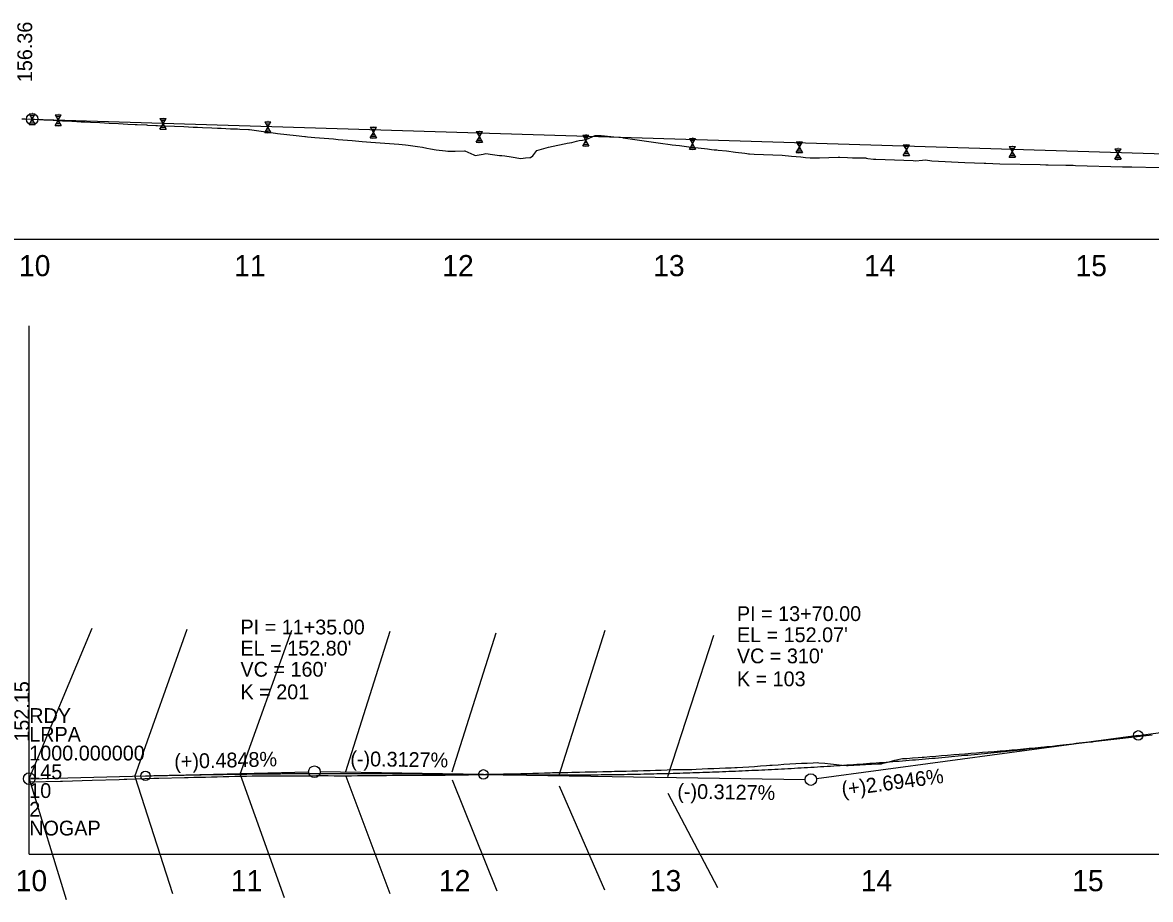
# Model space of a CAD drawing. Extents: x 573468 to 580768, y -57414 to -51768.
# Drawn here: x 573765 to 574299, y -54004 to -53589 of the extents above; entities that cross this region are included whole.
import ezdxf

# ---------------------------------------------------------------- set-up
doc = ezdxf.new("R2010")
doc.units = 0
for name, color, linetype in [('Exist Profile Cell', 7, 'Continuous'), ('Exist Vertical Profile Ground Line', 7, 'Continuous'), ('Exist Vertical Profile Horizontal Axis Label Major', 7, 'Continuous'), ('Pattern 2', 7, 'Continuous'), ('Prop Vertical Profile Curve Label', 7, 'Continuous'), ('Prop Vertical Profile Grade', 7, 'Continuous'), ('Prop Vertical Profile Grade Label', 7, 'Continuous'), ('Prop VPI Label', 7, 'Continuous'), ('Scratch_Level_2', 7, 'Continuous')]:
    doc.layers.add(name, color=color, linetype=linetype)

msp = doc.modelspace()

# ---------------------------------------------------------------- linework, layer by layer
at = {"layer": 'Exist Profile Cell'}
for p, q in [((573531.99, -53691.24), (576075.95, -53691.24)), ((573768.56, -53982.27), (573768.56, -53732.27)), ((573768.56, -53982.27), (574901.26, -53982.27)), ((573768.56, -53982.27), (573768.56, -53982.27))]:
    msp.add_line(p, q, dxfattribs=at)
at = {"layer": 'Exist Vertical Profile Ground Line'}
for points in [[(573765.07, -53634.27), (573766.54, -53634.33), (573770.15, -53634.46), (573770.97, -53634.51), (573775.39, -53634.73), (573779.82, -53634.95), (573784.24, -53635.17), (573788.67, -53635.4), (573789.01, -53635.41), (573793.1, -53635.63), (573793.67, -53635.66), (573794.01, -53635.68), (573794.97, -53635.73), (573797.52, -53635.86), (573801.95, -53636.08), (573806.37, -53636.3), (573810.8, -53636.52), (573815.22, -53636.75), (573818.64, -53636.93), (573819.65, -53636.97), (573824.07, -53637.19), (573824.55, -53637.21), (573828.5, -53637.41), (573829.22, -53637.45), (573832.92, -53637.6), (573837.35, -53637.78)], [(573837.35, -53637.78), (573841.77, -53637.96), (573846.2, -53638.15), (573848.2, -53638.23), (573850.63, -53638.35), (573855.05, -53638.56), (573857.64, -53638.69), (573859.48, -53638.76), (573863.9, -53638.94), (573867.13, -53639.07), (573868.33, -53639.13), (573872.39, -53639.34), (573872.75, -53639.39), (573877.18, -53640), (573881.6, -53640.6), (573885.06, -53641.07), (573886.03, -53641.18), (573890.45, -53641.66), (573894.88, -53642.14), (573898.98, -53642.58), (573899.31, -53642.62), (573900.28, -53642.74), (573903.73, -53643.04), (573908.16, -53643.43), (573912.58, -53643.82), (573914.76, -53644), (573917.01, -53644.2), (573921.43, -53644.57), (573923.07, -53644.7), (573926.15, -53644.93), (573930.28, -53645.26), (573934.71, -53645.61), (573939.13, -53645.95), (573943.56, -53646.28), (573946.67, -53646.52), (573947.98, -53646.71), (573952.41, -53647.33), (573954.69, -53647.65), (573956.84, -53648.13), (573958.5, -53648.51), (573961.26, -53648.87), (573965.69, -53649.44), (573966.66, -53649.56), (573970.11, -53649.5), (573974.54, -53649.41), (573974.84, -53649.41), (573978.96, -53651.33), (573979.62, -53651.63), (573983.39, -53650.96), (573984.76, -53650.71), (573987.81, -53651.14), (573991.13, -53651.61), (573992.24, -53651.7), (573993.65, -53651.84), (573996.66, -53652.3), (574001.22, -53653.08), (574003.48, -53652.77), (574005.52, -53652.54), (574005.86, -53652.5), (574007.02, -53651.82), (574008.78, -53649.28), (574009.94, -53648.95), (574014.37, -53647.67), (574018.79, -53646.73), (574022.51, -53645.95), (574023.22, -53645.84), (574025.37, -53645.5), (574027.64, -53644.91), (574028.85, -53644.6), (574030.44, -53644.31), (574032.07, -53644.03), (574032.5, -53643.96), (574036.49, -53642.14), (574039.32, -53642.24), (574040.92, -53642.39), (574045.34, -53642.8), (574047.73, -53643.02), (574049.33, -53643.17), (574049.77, -53643.23), (574054.19, -53643.87), (574058.62, -53644.5), (574063.05, -53645.13), (574067.47, -53645.76), (574071.9, -53646.39), (574072.99, -53646.54), (574076.32, -53646.96), (574080.75, -53647.51), (574082.04, -53647.67), (574085.17, -53648.03), (574089.6, -53648.54), (574091.47, -53648.76), (574092.73, -53648.9), (574094.02, -53649.02), (574094.7, -53649.09), (574098.62, -53649.4), (574102.87, -53649.99), (574107.3, -53650.59), (574108.2, -53650.71), (574109.08, -53650.82), (574109.45, -53650.85), (574111.72, -53650.93)], [(574111.72, -53650.93), (574116.15, -53651.1), (574120.58, -53651.26), (574125, -53651.43), (574129.43, -53651.88), (574133.85, -53652.33), (574135.97, -53652.54), (574138.28, -53652.7), (574139.65, -53652.79), (574142.7, -53652.71), (574147.13, -53652.6), (574151.55, -53652.49), (574152.35, -53652.47), (574155.98, -53652.61), (574158.31, -53652.7), (574160.4, -53652.71), (574164.52, -53652.74), (574164.83, -53652.83), (574165.49, -53653.03), (574168.24, -53653.38), (574169.26, -53653.41), (574173.68, -53653.58), (574178.11, -53653.74), (574182.53, -53653.9), (574186.96, -53654.06), (574188.17, -53654.1), (574191.38, -53653.84), (574192.77, -53653.73), (574195.81, -53654.09), (574211.43, -53654.92), (574220.55, -53655.18), (574221.36, -53655.21), (574227.98, -53655.52), (574247.06, -53655.81), (574249.75, -53655.98), (574250.98, -53656.06), (574259.21, -53656.25), (574262.76, -53656.27), (574263.91, -53656.38), (574286.08, -53656.96), (574290.51, -53656.97), (574303.67, -53657.3)], [(574264.06, -53929.85), (574266.83, -53929.55), (574269.59, -53929.25), (574271.85, -53929.01), (574272.36, -53928.95), (574275.12, -53928.62), (574277.52, -53928.33), (574277.89, -53928.29), (574280.65, -53927.97), (574283.42, -53927.66), (574286.18, -53927.34), (574288.95, -53927.03), (574291.72, -53926.73), (574294.48, -53926.42), (574297.25, -53926.12), (574300.16, -53925.8)], [(574040.14, -53943.16), (574042.83, -53943.1), (574044.25, -53943.07), (574045.6, -53943.04), (574048.36, -53942.99), (574051.13, -53942.93), (574053.89, -53942.88), (574056.66, -53942.82), (574059.42, -53942.72), (574062.19, -53942.61), (574062.54, -53942.6), (574064.95, -53942.51), (574067.72, -53942.42), (574070.48, -53942.33), (574073.25, -53942.24), (574076.02, -53942.15), (574076.65, -53942.13), (574078.78, -53942.12), (574081.55, -53942.1), (574082.22, -53942.1), (574084.31, -53942.01), (574087.08, -53941.89), (574089.84, -53941.78), (574092.61, -53941.67), (574095.37, -53941.56), (574098.14, -53941.46), (574098.88, -53941.43), (574100.9, -53941.33), (574102.61, -53941.26), (574103.67, -53941.19), (574106.43, -53941.02), (574109.2, -53940.85), (574111.97, -53940.68), (574114.81, -53940.51), (574117.5, -53940.31), (574119.11, -53940.18), (574120.26, -53940.1), (574123.03, -53939.92), (574125.79, -53939.73), (574128.56, -53939.55), (574131.47, -53939.36), (574134.09, -53939.19), (574134.51, -53939.17), (574136.52, -53939.19), (574136.85, -53939.17), (574139.62, -53939.01), (574141.6, -53938.9), (574142.38, -53938.97), (574145.15, -53939.24), (574147.92, -53939.51), (574150.68, -53939.78), (574153.45, -53940.05), (574155.43, -53940.25), (574156.21, -53940.21), (574158.98, -53940.07), (574161.74, -53939.93), (574164.51, -53939.79), (574167.27, -53939.66), (574170.04, -53939.52), (574171.97, -53939.42), (574172.8, -53939.21), (574175.57, -53938.49), (574178.33, -53937.78), (574181.13, -53937.06), (574182, -53937.03), (574183.99, -53936.93), (574186.63, -53936.73), (574189.4, -53936.51), (574191.29, -53936.37), (574192.16, -53936.29), (574194.93, -53936.05), (574197.69, -53935.81), (574200.46, -53935.57), (574203.22, -53935.33), (574206.28, -53935.07), (574208.75, -53934.89), (574211.52, -53934.7), (574213.03, -53934.59), (574214.28, -53934.49), (574217.05, -53934.26), (574219.82, -53934.04), (574222.58, -53933.82), (574225.35, -53933.6), (574228.11, -53933.38), (574228.56, -53933.35), (574230.88, -53933.15), (574232.45, -53933.02), (574233.64, -53932.91), (574236.41, -53932.65), (574239.17, -53932.4), (574241.94, -53932.14), (574244.7, -53931.89), (574247.47, -53931.64), (574249.13, -53931.5), (574250.23, -53931.37), (574253, -53931.06), (574254.98, -53930.84), (574255.77, -53930.76), (574258.53, -53930.45), (574261.3, -53930.15), (574264.06, -53929.85)], [(573768.56, -53948.04), (573769.34, -53948.02), (573783.28, -53947.67), (573784.34, -53947.63), (573798.31, -53947.2), (573811.09, -53946.84), (573813.42, -53946.78), (573814.8, -53946.73), (573827.54, -53946.32), (573829.92, -53946.28), (573842.05, -53945.9), (573843.72, -53945.89), (573846.49, -53945.82), (573848.57, -53945.76), (573849.25, -53945.76), (573851.7, -53945.76), (573852.02, -53945.76), (573854.78, -53945.68), (573857.55, -53945.61), (573860.31, -53945.54), (573863.08, -53945.47), (573865.85, -53945.4), (573868.61, -53945.33), (573871.38, -53945.26), (573874.14, -53945.19), (573875.29, -53945.16), (573876.91, -53945.19), (573879.23, -53945.23), (573879.67, -53945.22), (573882.44, -53945.19), (573883.4, -53945.19), (573885.2, -53945.22), (573886.03, -53945.23), (573887.97, -53945.21), (573890.73, -53945.19), (573893.5, -53945.16), (573896.26, -53945.14), (573899.03, -53945.12), (573901.8, -53945.11), (573904.56, -53945.09), (573907.33, -53945.07), (573908.9, -53945.06), (573910.09, -53945.08), (573912.86, -53945.12), (573915.62, -53945.16), (573918.39, -53945.14), (573920.5, -53945.13), (573921.15, -53945.12), (573923.92, -53945.09), (573926.68, -53945.06), (573929.45, -53945.03), (573932.21, -53945), (573934.98, -53944.97), (573937.75, -53944.94), (573940.51, -53944.92), (573941.05, -53944.92), (573943.28, -53944.91), (573944.86, -53944.9), (573946.04, -53944.89), (573948.81, -53944.87), (573951.57, -53944.85), (573954.34, -53944.83), (573957.1, -53944.81), (573959.87, -53944.8), (573962.63, -53944.79), (573963.06, -53944.78), (573965.4, -53944.78), (573967.77, -53944.77), (573968.16, -53944.76), (573969.28, -53944.74), (573970.93, -53944.72), (573973.75, -53944.69), (573976.46, -53944.63), (573979.23, -53944.57), (573981.99, -53944.51), (573984.76, -53944.45), (573987.52, -53944.4), (573990.29, -53944.34), (573993.05, -53944.29), (573995.44, -53944.25), (573995.82, -53944.24), (573998.58, -53944.19), (574000.13, -53944.17), (574001.35, -53944.13), (574004.11, -53944.04), (574006.88, -53943.95), (574009.65, -53943.86), (574012.41, -53943.78), (574015.18, -53943.69), (574016.21, -53943.66), (574017.94, -53943.64), (574020.34, -53943.62), (574020.71, -53943.61), (574023.47, -53943.54), (574025.36, -53943.5), (574026.24, -53943.48), (574029, -53943.41), (574031.77, -53943.35), (574034.53, -53943.28), (574037.3, -53943.22), (574040.14, -53943.16)]]:
    msp.add_lwpolyline(points, dxfattribs=at)
at = {"layer": 'Pattern 2'}
for p, q in [((573768.47, -53631.94), (573771.4, -53631.94)), ((573768.47, -53631.94), (573769.94, -53634.44)), ((573768.96, -53632.78), (573770.91, -53632.78)), ((573769.45, -53633.61), (573770.43, -53633.61)), ((573769.94, -53634.44), (573771.4, -53631.94)), ((573780.82, -53632.39), (573783.75, -53632.39)), ((573780.82, -53632.39), (573782.29, -53634.89)), ((573781.31, -53633.23), (573783.26, -53633.23)), ((573782.29, -53634.89), (573783.75, -53632.39)), ((573768.47, -53636.94), (573769.94, -53634.44)), ((573768.47, -53636.94), (573771.4, -53636.94)), ((573768.96, -53636.11), (573770.91, -53636.11)), ((573769.45, -53635.28), (573770.43, -53635.28)), ((573769.94, -53634.44), (573771.4, -53636.94)), ((573780.82, -53637.39), (573782.29, -53634.89)), ((573780.82, -53637.39), (573783.75, -53637.39)), ((573781.31, -53636.56), (573783.26, -53636.56)), ((573781.8, -53634.06), (573782.78, -53634.06)), ((573781.8, -53635.73), (573782.78, -53635.73)), ((573782.29, -53634.89), (573783.75, -53637.39)), ((573830.45, -53634.09), (573833.38, -53634.09)), ((573830.45, -53634.09), (573831.92, -53636.59)), ((573830.45, -53639.09), (573831.92, -53636.59)), ((573830.94, -53634.93), (573832.89, -53634.93)), ((573830.94, -53638.26), (573832.89, -53638.26)), ((573831.43, -53635.76), (573832.41, -53635.76)), ((573831.43, -53637.43), (573832.41, -53637.43)), ((573831.92, -53636.59), (573833.38, -53634.09)), ((573831.92, -53636.59), (573833.38, -53639.09)), ((573880.06, -53635.74), (573882.99, -53635.74)), ((573880.06, -53635.74), (573881.53, -53638.24)), ((573880.06, -53640.74), (573881.53, -53638.24)), ((573880.55, -53636.58), (573882.5, -53636.58)), ((573881.04, -53637.41), (573882.02, -53637.41)), ((573881.53, -53638.24), (573882.99, -53635.74)), ((573881.53, -53638.24), (573882.99, -53640.74)), ((573929.99, -53638.29), (573932.92, -53638.29)), ((573929.99, -53638.29), (573931.46, -53640.79)), ((573931.46, -53640.79), (573932.92, -53638.29)), ((573830.45, -53639.09), (573833.38, -53639.09)), ((573880.06, -53640.74), (573882.99, -53640.74)), ((573880.55, -53639.91), (573882.5, -53639.91)), ((573881.04, -53639.08), (573882.02, -53639.08)), ((573929.99, -53643.29), (573931.46, -53640.79)), ((573929.99, -53643.29), (573932.92, -53643.29)), ((573930.48, -53639.13), (573932.43, -53639.13)), ((573930.48, -53642.46), (573932.43, -53642.46)), ((573930.97, -53639.96), (573931.95, -53639.96)), ((573930.97, -53641.63), (573931.95, -53641.63)), ((573931.46, -53640.79), (573932.92, -53643.29)), ((573980.2, -53640.34), (573983.13, -53640.34)), ((573980.2, -53640.34), (573981.67, -53642.84)), ((573980.2, -53645.34), (573981.67, -53642.84)), ((573980.69, -53641.18), (573982.64, -53641.18)), ((573981.18, -53642.01), (573982.16, -53642.01)), ((573981.18, -53643.68), (573982.16, -53643.68)), ((573981.67, -53642.84), (573983.13, -53640.34)), ((573981.67, -53642.84), (573983.13, -53645.34)), ((574030.59, -53642.04), (574033.52, -53642.04)), ((574030.59, -53642.04), (574032.06, -53644.54)), ((574031.08, -53642.88), (574033.03, -53642.88)), ((574031.57, -53643.71), (574032.55, -53643.71)), ((574032.06, -53644.54), (574033.52, -53642.04)), ((574081.08, -53643.64), (574084.01, -53643.64)), ((574081.08, -53643.64), (574082.55, -53646.14)), ((574082.55, -53646.14), (574084.01, -53643.64)), ((573980.2, -53645.34), (573983.13, -53645.34)), ((573980.69, -53644.51), (573982.64, -53644.51)), ((574030.59, -53647.04), (574032.06, -53644.54)), ((574030.59, -53647.04), (574033.52, -53647.04)), ((574031.08, -53646.21), (574033.03, -53646.21)), ((574031.57, -53645.38), (574032.55, -53645.38)), ((574032.06, -53644.54), (574033.52, -53647.04)), ((574081.08, -53648.64), (574082.55, -53646.14)), ((574081.08, -53648.64), (574084.01, -53648.64)), ((574081.57, -53644.48), (574083.52, -53644.48)), ((574081.57, -53647.81), (574083.52, -53647.81)), ((574082.06, -53645.31), (574083.04, -53645.31)), ((574082.06, -53646.98), (574083.04, -53646.98)), ((574082.55, -53646.14), (574084.01, -53648.64)), ((574131.67, -53645.19), (574134.6, -53645.19)), ((574131.67, -53645.19), (574133.14, -53647.69)), ((574131.67, -53650.19), (574133.14, -53647.69)), ((574132.16, -53646.03), (574134.11, -53646.03)), ((574132.16, -53649.36), (574134.11, -53649.36)), ((574132.65, -53646.86), (574133.63, -53646.86)), ((574132.65, -53648.53), (574133.63, -53648.53)), ((574133.14, -53647.69), (574134.6, -53645.19)), ((574133.14, -53647.69), (574134.6, -53650.19)), ((574182.32, -53646.59), (574185.25, -53646.59)), ((574182.32, -53646.59), (574183.79, -53649.09)), ((574182.32, -53651.59), (574183.79, -53649.09)), ((574182.81, -53647.43), (574184.76, -53647.43)), ((574183.3, -53648.26), (574184.28, -53648.26)), ((574183.79, -53649.09), (574185.25, -53646.59)), ((574183.79, -53649.09), (574185.25, -53651.59)), ((574232.47, -53647.44), (574235.4, -53647.44)), ((574232.47, -53647.44), (574233.94, -53649.94)), ((574232.96, -53648.28), (574234.91, -53648.28)), ((574233.45, -53649.11), (574234.43, -53649.11)), ((574233.94, -53649.94), (574235.4, -53647.44)), ((574282.47, -53648.44), (574285.4, -53648.44)), ((574282.47, -53648.44), (574283.94, -53650.94)), ((574282.96, -53649.28), (574284.91, -53649.28)), ((574283.94, -53650.94), (574285.4, -53648.44)), ((574131.67, -53650.19), (574134.6, -53650.19)), ((574182.32, -53651.59), (574185.25, -53651.59)), ((574182.81, -53650.76), (574184.76, -53650.76)), ((574183.3, -53649.93), (574184.28, -53649.93)), ((574232.47, -53652.44), (574233.94, -53649.94)), ((574232.47, -53652.44), (574235.4, -53652.44)), ((574232.96, -53651.61), (574234.91, -53651.61)), ((574233.45, -53650.78), (574234.43, -53650.78)), ((574233.94, -53649.94), (574235.4, -53652.44)), ((574282.47, -53653.44), (574283.94, -53650.94)), ((574282.47, -53653.44), (574285.4, -53653.44)), ((574282.96, -53652.61), (574284.91, -53652.61)), ((574283.45, -53650.11), (574284.43, -53650.11)), ((574283.45, -53651.78), (574284.43, -53651.78)), ((574283.94, -53650.94), (574285.4, -53653.44))]:
    msp.add_line(p, q, dxfattribs=at)
at = {"layer": 'Prop Vertical Profile Curve Label'}
for centre in [(574293.56, -53926.04), (573823.56, -53945.19), (573983.56, -53944.5), (573983.56, -53944.5)]:
    msp.add_circle(centre, 2.25, dxfattribs=at)
at = {"layer": 'Prop Vertical Profile Grade'}
for p, q in [((573769.94, -53634.44), (574570.13, -53658.85)), ((574293.56, -53926.04), (574355.31, -53917.72)), ((573768.56, -53946.52), (573823.56, -53945.19))]:
    msp.add_line(p, q, dxfattribs=at)
for points in [[(573983.56, -53944.5), (573989.76, -53944.59), (573995.96, -53944.66), (574002.16, -53944.71), (574008.36, -53944.74), (574014.56, -53944.75), (574020.76, -53944.75), (574026.96, -53944.72), (574033.16, -53944.68), (574039.36, -53944.62), (574045.56, -53944.54), (574051.76, -53944.44), (574057.96, -53944.32), (574064.16, -53944.18), (574070.36, -53944.03), (574076.56, -53943.86), (574082.76, -53943.66), (574088.96, -53943.45), (574095.16, -53943.22), (574101.36, -53942.98), (574107.56, -53942.71), (574113.76, -53942.42), (574119.96, -53942.12), (574126.16, -53941.8), (574132.36, -53941.46), (574138.56, -53941.1), (574144.76, -53940.72), (574150.96, -53940.32), (574157.16, -53939.91), (574163.36, -53939.47), (574169.56, -53939.02), (574175.76, -53938.55), (574181.96, -53938.06), (574188.16, -53937.55), (574194.36, -53937.02), (574200.56, -53936.47), (574206.76, -53935.91), (574212.96, -53935.32), (574219.16, -53934.72), (574225.36, -53934.1), (574231.56, -53933.46), (574237.76, -53932.8), (574243.96, -53932.13), (574250.16, -53931.43), (574256.36, -53930.72), (574262.56, -53929.98), (574268.76, -53929.23), (574274.96, -53928.46), (574281.16, -53927.67), (574287.36, -53926.87), (574293.56, -53926.04)], [(573823.56, -53945.19), (573826.76, -53945.11), (573829.96, -53945.04), (573833.16, -53944.97), (573836.36, -53944.9), (573839.56, -53944.83), (573842.76, -53944.77), (573845.96, -53944.71), (573849.16, -53944.65), (573852.36, -53944.59), (573855.56, -53944.54), (573858.76, -53944.49), (573861.96, -53944.44), (573865.16, -53944.39), (573868.36, -53944.35), (573871.56, -53944.31), (573874.76, -53944.27), (573877.96, -53944.24), (573881.16, -53944.2), (573884.36, -53944.17), (573887.56, -53944.15), (573890.76, -53944.12), (573893.96, -53944.1), (573897.16, -53944.08), (573900.36, -53944.06), (573903.56, -53944.05), (573906.76, -53944.03), (573909.96, -53944.02), (573913.16, -53944.02), (573916.36, -53944.01), (573919.56, -53944.01), (573922.76, -53944.01), (573925.96, -53944.01), (573929.16, -53944.02), (573932.36, -53944.03), (573935.56, -53944.04), (573938.76, -53944.05), (573941.96, -53944.06), (573945.16, -53944.08), (573948.36, -53944.1), (573951.56, -53944.13), (573954.76, -53944.15), (573957.96, -53944.18), (573961.16, -53944.21), (573964.36, -53944.25), (573967.56, -53944.28), (573970.76, -53944.32), (573973.96, -53944.36), (573977.16, -53944.4), (573980.36, -53944.45), (573983.56, -53944.5)]]:
    msp.add_spline(points, degree=3, dxfattribs=at)
at = {"layer": 'Prop VPI Label'}
for p, q in [((574293.56, -53926.04), (574141.29, -53946.56)), ((573823.56, -53945.19), (573900.82, -53943.32)), ((573983.56, -53944.5), (573906.31, -53943.29)), ((573983.56, -53944.5), (574135.82, -53946.88))]:
    msp.add_line(p, q, dxfattribs=at)
for centre in [(573769.94, -53634.44), (573903.56, -53943.25), (573768.56, -53946.52), (574138.56, -53946.92)]:
    msp.add_circle(centre, 2.75, dxfattribs=at)
at = {"layer": 'Scratch_Level_2'}
for p, q in [((573768.56, -53946.52), (573798.28, -53875.22)), ((573818.52, -53945.47), (573843.34, -53875.72)), ((573868.39, -53944.37), (573892.9, -53876.22)), ((573918.4, -53943.17), (573939.46, -53876.72)), ((573968.72, -53943.27), (573989.66, -53877.44)), ((574019.5, -53944.92), (574041.15, -53876.29)), ((574070.9, -53945.52), (574092.64, -53878.58)), ((573768.56, -53946.52), (573785.98, -54003.66)), ((573818.52, -53945.47), (573836.33, -54000.8)), ((573868.39, -53944.52), (573889.25, -54002.8)), ((573918.4, -53945.27), (573939.31, -54000.8)), ((573968.72, -53947.12), (573989.95, -53999.65)), ((574019.5, -53949.87), (574040.87, -53999.08)), ((574070.9, -53953.37), (574094.36, -53997.94))]:
    msp.add_line(p, q, dxfattribs=at)

# ---------------------------------------------------------------- texts
at = {"layer": 'Exist Profile Cell'}
for s, p in [('RDY', (573768.56, -53920.15)), ('LRPA', (573768.56, -53929.03)), ('1000.000000', (573768.56, -53937.9)), ('145', (573768.56, -53946.78)), ('10', (573768.56, -53955.65)), ('2', (573768.56, -53964.52)), ('NOGAP', (573768.56, -53973.4))]:
    msp.add_text(s, height=7, dxfattribs=at).set_placement(p)
at = {"layer": 'Exist Vertical Profile Horizontal Axis Label Major'}
for s, p in [('10', (573763.71, -53708.74)), ('11', (573865.55, -53708.74)), ('12', (573964.1, -53708.74)), ('13', (574063.94, -53708.74)), ('14', (574163.78, -53708.74)), ('15', (574263.87, -53708.74)), ('10', (573762.15, -53999.77)), ('11', (573863.99, -53999.77)), ('12', (573962.54, -53999.77)), ('13', (574062.37, -53999.77)), ('14', (574162.21, -53999.77)), ('15', (574262.31, -53999.77))]:
    msp.add_text(s, height=10, dxfattribs=at).set_placement(p)
at = {"layer": 'Pattern 2'}
for s, p in [('6"', (573769.82, -53631.84)), ('6"', (573782.17, -53632.29)), ('6"', (573831.8, -53633.99)), ('-6"', (573769.36, -53637.55)), ('-6"', (573781.71, -53638)), ('6"', (573881.41, -53635.64)), ('6"', (573931.34, -53638.19)), ('-6"', (573831.34, -53639.7)), ('-6"', (573880.95, -53641.35)), ('-6"', (573930.88, -53643.9)), ('6"', (573981.55, -53640.24)), ('6"', (574031.94, -53641.94)), ('6"', (574082.43, -53643.54)), ('-6"', (573981.09, -53645.95)), ('-6"', (574031.48, -53647.65)), ('-6"', (574081.97, -53649.25)), ('6"', (574133.02, -53645.09)), ('6"', (574183.67, -53646.49)), ('6"', (574233.82, -53647.34)), ('6"', (574283.82, -53648.34)), ('-6"', (574132.56, -53650.8)), ('-6"', (574183.21, -53652.2)), ('-6"', (574233.36, -53653.05)), ('-6"', (574283.36, -53654.05))]:
    msp.add_text(s, height=0.5, rotation=360, dxfattribs=at).set_placement(p)
at = {"layer": 'Prop Vertical Profile Curve Label'}
for s, p in [("VC = 310'", (574103.56, -53891.92)), ("VC = 160'", (573868.56, -53898.25)), ('K = 103', (574103.56, -53902.77)), ('K = 201', (573868.56, -53908.93))]:
    msp.add_text(s, height=7, dxfattribs=at).set_placement(p)
at = {"layer": 'Prop Vertical Profile Grade Label'}
for s, rotation, p in [('(+)0.4848%', 1.3886, (573837.29, -53941.85)), ('(-)0.3127%', 359.1042, (573920.52, -53940.51)), ('(+)2.6946%', 7.6731, (574153.56, -53954.99)), ('(-)0.3127%', 359.1042, (574075.33, -53955.94))]:
    msp.add_text(s, height=7, rotation=rotation, dxfattribs=at).set_placement(p)
at = {"layer": 'Prop VPI Label'}
for s, p in [('156.36', (573769.94, -53616.94)), ('152.15', (573768.56, -53929.02))]:
    msp.add_text(s, height=7, rotation=90, dxfattribs=at).set_placement(p)
for s, p in [('PI = 13+70.00', (574103.56, -53871.92)), ('PI = 11+35.00', (573868.56, -53878.25)), ("EL = 152.07'", (574103.56, -53881.92)), ("EL = 152.80'", (573868.56, -53888.25))]:
    msp.add_text(s, height=7, dxfattribs=at).set_placement(p)

doc.saveas('drawing.dxf')
